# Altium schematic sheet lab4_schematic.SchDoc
size A4; Author: Michał Wojna; CompanyName: AGH; Revision: 1; SheetNumber: 1; SheetTotal: 3; SPICEModelCacheRHFFZEVK: <root> / <DocumentId>RHFFZEVK</DocumentId> / </root>
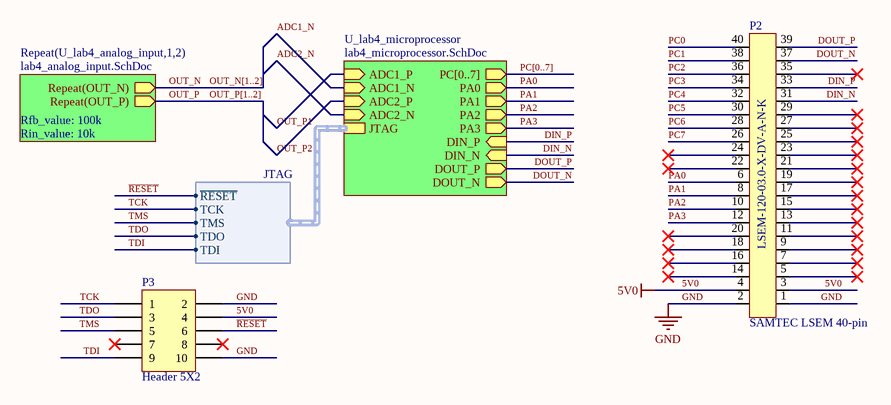
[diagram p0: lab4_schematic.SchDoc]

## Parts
P2  SAMTEC LSEM 40-pin  [LSEM-120-03.0-L-DV-A-N-K-TR]
P3  Header 5X2  [HDR2X5]

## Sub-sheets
Repeat(U_lab4_analog_input,1,2) = lab4_analog_input.SchDoc: Repeat(OUT_P) (out), Repeat(OUT_N) (out)  | Rfb_value: 100k; Rin_value: 10k
U_lab4_microprocessor = lab4_microprocessor.SchDoc: PC[0..7] (out), PA0 (out), PA1 (out), PA2 (out), PA3 (out), JTAG (harness JTAG), ADC2_P (in), ADC2_N (in), ADC1_N (in), ADC1_P (in), DIN_P (in), DIN_N (in), DOUT_P (out), DOUT_N (out)

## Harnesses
JTAG: ~{RESET}, TCK, TMS, TDO, TDI

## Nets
5V0: P2.3 P2.4 P3.4
GND: P2.1 P2.2 P3.2 P3.10
~{RESET}: P3.6 ; sheet U_lab4_microprocessor/JTAG.~{RESET}
DIN_N: P2.31 ; sheet U_lab4_microprocessor/DIN_N
DIN_P: P2.33 ; sheet U_lab4_microprocessor/DIN_P
DOUT_N: P2.37 ; sheet U_lab4_microprocessor/DOUT_N
DOUT_P: P2.39 ; sheet U_lab4_microprocessor/DOUT_P
PA0: P2.6 ; sheet U_lab4_microprocessor/PA0
PA1: P2.8 ; sheet U_lab4_microprocessor/PA1
PA2: P2.10 ; sheet U_lab4_microprocessor/PA2
PA3: P2.12 ; sheet U_lab4_microprocessor/PA3
PC0: P2.40
PC1: P2.38
PC2: P2.36
PC3: P2.34
PC4: P2.32
PC5: P2.30
PC6: P2.28
PC7: P2.26
TCK: P3.1 ; sheet U_lab4_microprocessor/JTAG.TCK
TDI: P3.9 ; sheet U_lab4_microprocessor/JTAG.TDI
TDO: P3.3 ; sheet U_lab4_microprocessor/JTAG.TDO
TMS: P3.5 ; sheet U_lab4_microprocessor/JTAG.TMS

Not connected (* = marked no-connect by the designer): P2 5(3)* 7(4)* 9(5)* 11(6)* 13(7)* 14(8)* 15(8)* 16(9)* 17(9)* 18(10)* 19(10)* 20(11)* 21(11)* 22(12)* 23(12)* 24(13)* 25(13)* 27(14)* 29(15)* 35(18)*; P3 7* 8*

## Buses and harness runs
bus OUT_N[1..2]
bus OUT_P[1..2]
bus PC[0..7] = sheet U_lab4_microprocessor/PC[0..7]

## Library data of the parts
P2 = LSEM-120-03.0-X-DV-A-N-K
P3 = Header 5X2: Header, 5-Pin, Dual row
